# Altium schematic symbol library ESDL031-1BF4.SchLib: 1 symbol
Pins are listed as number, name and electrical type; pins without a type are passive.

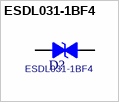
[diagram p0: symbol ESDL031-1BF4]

## ESDL031-1BF4
designator D?
footprint ST_0201B-Flat
pins: 1, 2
